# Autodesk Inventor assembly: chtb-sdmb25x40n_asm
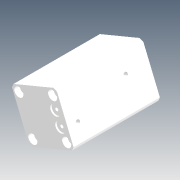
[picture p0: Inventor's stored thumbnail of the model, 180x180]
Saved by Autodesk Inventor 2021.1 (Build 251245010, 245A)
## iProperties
Company: Microsoft
Created: 2018-05
Part Number: chtb-sdmb25x40n_asm
Description: STEP AP214
Document SubType Name: Assembly
Designer: user
Title: chtb-sdmb25x40n_asm.STEP
Author: Windows
Revision Number: ÈÎºÎ
Sending System: SolidWorks 2015
Preprocessor: SwSTEP 2.0
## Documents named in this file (4)
- D:\Vault_2016\Projekty\Clamptek\Hydraulic\CHTB\CHTB-25\Inventor\chtb-sdmb25x40n\chtb-sdmb25x40n_asm.iam
- D:\Vault_2016\Projekty\Clamptek\Hydraulic\CHTB\CHTB-25\Inventor\chtb-sdmb25x40n\CHTB-25QG.ipt
- D:\Vault_2016\Projekty\Clamptek\Hydraulic\CHTB\CHTB-25\Inventor\chtb-sdmb25x40n\CHTB-SDMB25X40NBT.ipt
- D:\Vault_2016\Projekty\Clamptek\Hydraulic\CHTB\CHTB-25\Inventor\chtb-sdmb25x40n\CHTB-SDMB25X40NHSG.ipt
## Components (3 placed, 3 different names)
1. CHTB-25QG_1
2. CHTB-SDMB25X40NBT_2
3. CHTB-SDMB25X40NHSG_3
